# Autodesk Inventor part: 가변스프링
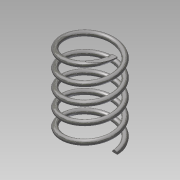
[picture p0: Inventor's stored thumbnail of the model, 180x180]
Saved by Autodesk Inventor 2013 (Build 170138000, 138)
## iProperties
Created: 2019-05
Part Number: 가변스프링
Material: 스테인리스강
Document SubType Name: Modeling
Designer: Administrator
Density: 8.08 g/cm^3
Mass: 7.87478 g
Surface Area: 19.7322 cm^2
Volume: 0.974601 cm^3
Author: Administrator
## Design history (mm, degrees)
sketch "스케치1"
  geometry: L1 (0, 0)-(10, 0); L2 (10, 0)-(10, 34); L3 (10, 34)-(0, 34); L4 (0, 34)-(0, 0); C1 r 1 at (10, 0)
  constraints: 8 end point, 2 parallel, 1 centre point, 1 coincident, 1 horizontal, 1 perpendicular
  dimensions: "d0" = 20 diameter of L2 L4; "d2" = 34 distance of L1.end L2.end (derived); "d3" = 2 diameter of C1
feature "코일1" sketch "스케치1" pitch "d4" = 10; turns "d6" = 5; dims "d5" = 34 (= d2), "d7" = 0, angle "d8" = 90 deg, angle "d9" = 90 deg, "d10" = 0, "d11" = 0
sketch "스케치2"
  geometry: L1 (34, 11.5)-(0, 11.5); L2 (0, 11.5)-(0, -11.5); L3 (0, -11.5)-(34, -11.5); L4 (34, -11.5)-(34, 11.5); 2 further points
  constraints: 8 end point, 2 parallel, 1 coincident, 1 horizontal, 1 midpoint, 1 perpendicular
  dimensions: "d12" = 23 distance of L1.end L2.end; "d14" = 34 distance of L2.end L3.end (derived)
extrude "돌출1" sketch "스케치2" stored distance "d15" = 23; taper "d16" = 0 deg
node "솔리드1"
